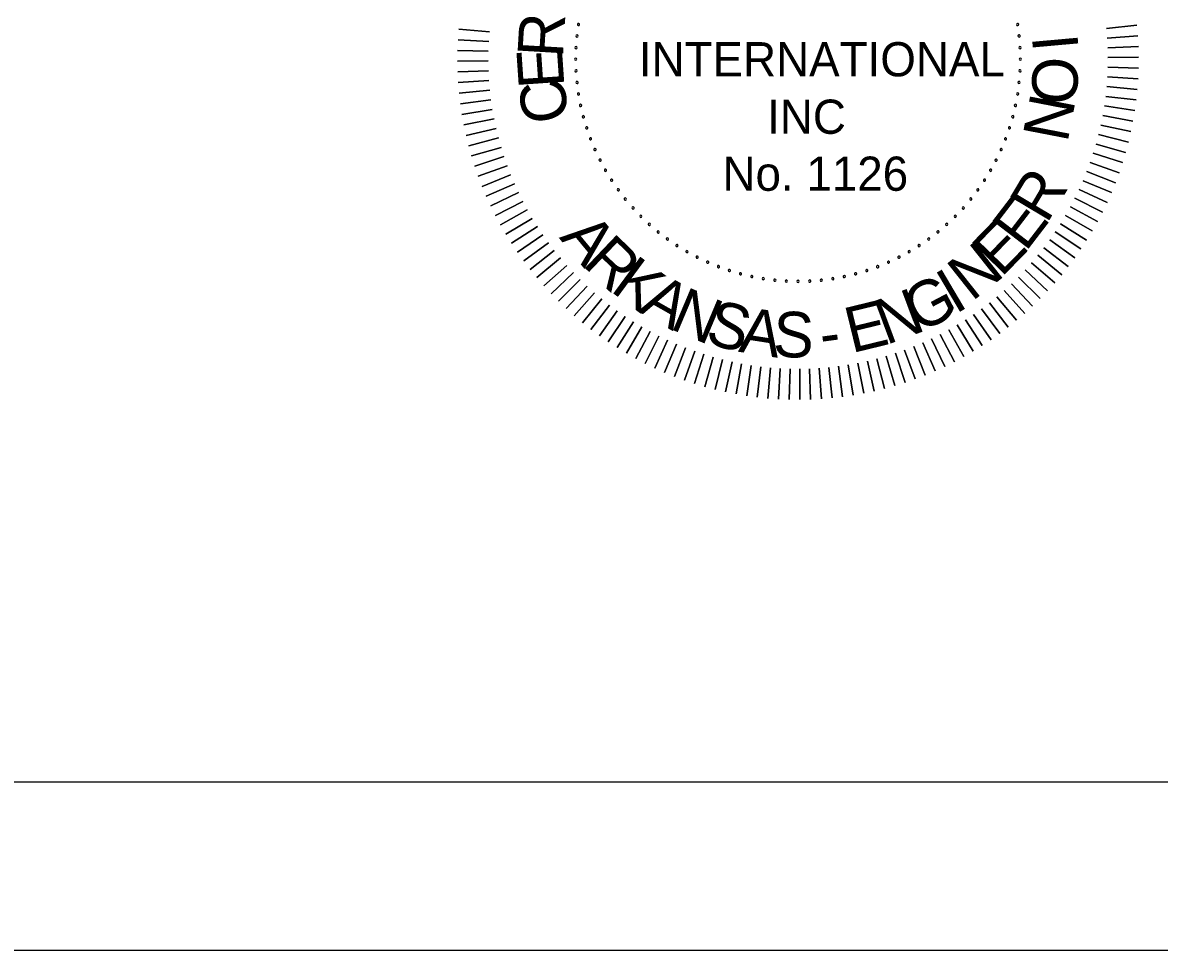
# Model space of a CAD drawing. Extents: x -0.96 to 2.36, y -0.12 to 0.92.
# Drawn here: x 1.0844 to 1.2247, y 0 to 0.1146 of the extents above; entities that cross this region are included whole.
import ezdxf

# ---------------------------------------------------------------- set-up
doc = ezdxf.new("R2010")
doc.units = 0
doc.layers.add('SHET_Border-Lines', color=7, linetype='Continuous')
doc.layers.add('STAMP_COA', color=7, linetype='Continuous')

msp = doc.modelspace()

# ---------------------------------------------------------------- linework, layer by layer
at = {"layer": 'SHET_Border-Lines'}
for points in [[(0, 0), (1.41666, 0), (1.41666, 0.91666), (0, 0.91666)], [(0.04167, 0.02083), (1.39583, 0.02083), (1.39583, 0.89583), (0.04167, 0.89583)]]:
    msp.add_lwpolyline(points, close=True, dxfattribs=at)
at = {"layer": 'STAMP_COA'}
for points in [[(1.14202, 0.11347), (1.13824, 0.11381)], [(1.13824, 0.11381), (1.14202, 0.11347)], [(1.22198, 0.11428), (1.21821, 0.1139)], [(1.21821, 0.1139), (1.22198, 0.11428)], [(1.14193, 0.11228), (1.13814, 0.11249)], [(1.13814, 0.11249), (1.14193, 0.11228)], [(1.2221, 0.11296), (1.21831, 0.1127)], [(1.21831, 0.1127), (1.2221, 0.11296)], [(1.14188, 0.11107), (1.13809, 0.11117)], [(1.13809, 0.11117), (1.14188, 0.11107)], [(1.22217, 0.11164), (1.21838, 0.1115)], [(1.21838, 0.1115), (1.22217, 0.11164)], [(1.14187, 0.10987), (1.13808, 0.10985)], [(1.13808, 0.10985), (1.14187, 0.10987)], [(1.22219, 0.11032), (1.2184, 0.1103)], [(1.2184, 0.1103), (1.22219, 0.11032)], [(1.14189, 0.10867), (1.1381, 0.10853)], [(1.1381, 0.10853), (1.14189, 0.10867)], [(1.22218, 0.109), (1.21839, 0.1091)], [(1.21839, 0.1091), (1.22218, 0.109)], [(1.14196, 0.10747), (1.13817, 0.10721)], [(1.13817, 0.10721), (1.14196, 0.10747)], [(1.22203, 0.10636), (1.21825, 0.1067)], [(1.21825, 0.1067), (1.22203, 0.10636)], [(1.22213, 0.10768), (1.21834, 0.1079)], [(1.21834, 0.1079), (1.22213, 0.10768)], [(1.14206, 0.10627), (1.13828, 0.10589)], [(1.13828, 0.10589), (1.14206, 0.10627)], [(1.22189, 0.10505), (1.21813, 0.1055)], [(1.21813, 0.1055), (1.22189, 0.10505)], [(1.1422, 0.10508), (1.13844, 0.10458)], [(1.13844, 0.10458), (1.1422, 0.10508)], [(1.14237, 0.10389), (1.13863, 0.10327)], [(1.13863, 0.10327), (1.14237, 0.10389)], [(1.22171, 0.10374), (1.21796, 0.10431)], [(1.21796, 0.10431), (1.22171, 0.10374)], [(1.14259, 0.10271), (1.13886, 0.10197)], [(1.13886, 0.10197), (1.14259, 0.10271)], [(1.22149, 0.10243), (1.21776, 0.10312)], [(1.21776, 0.10312), (1.22149, 0.10243)], [(1.14284, 0.10153), (1.13914, 0.10068)], [(1.13914, 0.10068), (1.14284, 0.10153)], [(1.22123, 0.10114), (1.21753, 0.10195)], [(1.21753, 0.10195), (1.22123, 0.10114)], [(1.14312, 0.10036), (1.13946, 0.0994)], [(1.13946, 0.0994), (1.14312, 0.10036)], [(1.22093, 0.09985), (1.21725, 0.10078)], [(1.21725, 0.10078), (1.22093, 0.09985)], [(1.14345, 0.0992), (1.13981, 0.09813)], [(1.13981, 0.09813), (1.14345, 0.0992)], [(1.22021, 0.09731), (1.21659, 0.09846)], [(1.21659, 0.09846), (1.22021, 0.09731)], [(1.22059, 0.09858), (1.21694, 0.09961)], [(1.21694, 0.09961), (1.22059, 0.09858)], [(1.14381, 0.09806), (1.14021, 0.09687)], [(1.14021, 0.09687), (1.14381, 0.09806)], [(1.1442, 0.09692), (1.14064, 0.09562)], [(1.14064, 0.09562), (1.1442, 0.09692)], [(1.21979, 0.09606), (1.21621, 0.09732)], [(1.21621, 0.09732), (1.21979, 0.09606)], [(1.14463, 0.0958), (1.14112, 0.09438)], [(1.14112, 0.09438), (1.14463, 0.0958)], [(1.21933, 0.09482), (1.21579, 0.0962)], [(1.21579, 0.0962), (1.21933, 0.09482)], [(1.1451, 0.09469), (1.14163, 0.09317)], [(1.14163, 0.09317), (1.1451, 0.09469)], [(1.21883, 0.0936), (1.21534, 0.09508)], [(1.21534, 0.09508), (1.21883, 0.0936)], [(1.1456, 0.0936), (1.14218, 0.09197)], [(1.14218, 0.09197), (1.1456, 0.0936)], [(1.21772, 0.0912), (1.21433, 0.0929)], [(1.21433, 0.0929), (1.21772, 0.0912)], [(1.21829, 0.09239), (1.21485, 0.09399)], [(1.21485, 0.09399), (1.21829, 0.09239)], [(1.14614, 0.09252), (1.14277, 0.09078)], [(1.14277, 0.09078), (1.14614, 0.09252)], [(1.1467, 0.09146), (1.14339, 0.08962)], [(1.14339, 0.08962), (1.1467, 0.09146)], [(1.2171, 0.09003), (1.21377, 0.09184)], [(1.21377, 0.09184), (1.2171, 0.09003)], [(1.14731, 0.09042), (1.14405, 0.08847)], [(1.14405, 0.08847), (1.14731, 0.09042)], [(1.21646, 0.08888), (1.21318, 0.09079)], [(1.21318, 0.09079), (1.21646, 0.08888)], [(1.14794, 0.0894), (1.14475, 0.08735)], [(1.14475, 0.08735), (1.14794, 0.0894)], [(1.21505, 0.08664), (1.2119, 0.08875)], [(1.2119, 0.08875), (1.21505, 0.08664)], [(1.21577, 0.08775), (1.21256, 0.08976)], [(1.21256, 0.08976), (1.21577, 0.08775)], [(1.14861, 0.0884), (1.14548, 0.08625)], [(1.14548, 0.08625), (1.14861, 0.0884)], [(1.1493, 0.08742), (1.14625, 0.08517)], [(1.14625, 0.08517), (1.1493, 0.08742)], [(1.2143, 0.08555), (1.21122, 0.08777)], [(1.21122, 0.08777), (1.2143, 0.08555)], [(1.15003, 0.08646), (1.14704, 0.08412)], [(1.14704, 0.08412), (1.15003, 0.08646)], [(1.21269, 0.08346), (1.20976, 0.08586)], [(1.20976, 0.08586), (1.21269, 0.08346)], [(1.21351, 0.08449), (1.2105, 0.0868)], [(1.2105, 0.0868), (1.21351, 0.08449)], [(1.15079, 0.08553), (1.14788, 0.0831)], [(1.14788, 0.0831), (1.15079, 0.08553)], [(1.15157, 0.08462), (1.14874, 0.0821)], [(1.14874, 0.0821), (1.15157, 0.08462)], [(1.21184, 0.08245), (1.20898, 0.08494)], [(1.20898, 0.08494), (1.21184, 0.08245)], [(1.15239, 0.08374), (1.14964, 0.08112)], [(1.14964, 0.08112), (1.15239, 0.08374)], [(1.15323, 0.08288), (1.15056, 0.08018)], [(1.15056, 0.08018), (1.15323, 0.08288)], [(1.21004, 0.08051), (1.20734, 0.08318)], [(1.20734, 0.08318), (1.21004, 0.08051)], [(1.21095, 0.08146), (1.20818, 0.08405)], [(1.20818, 0.08405), (1.21095, 0.08146)], [(1.1541, 0.08204), (1.15151, 0.07927)], [(1.15151, 0.07927), (1.1541, 0.08204)], [(1.20812, 0.07869), (1.2056, 0.08152)], [(1.2056, 0.08152), (1.20812, 0.07869)], [(1.2091, 0.07959), (1.20648, 0.08234)], [(1.20648, 0.08234), (1.2091, 0.07959)], [(1.1525, 0.07838), (1.15499, 0.08124)], [(1.15499, 0.08124), (1.1525, 0.07838)], [(1.15351, 0.07753), (1.15591, 0.08047)], [(1.15591, 0.08047), (1.15351, 0.07753)], [(1.20712, 0.07783), (1.20469, 0.08074)], [(1.20469, 0.08074), (1.20712, 0.07783)], [(1.15454, 0.07671), (1.15685, 0.07972)], [(1.15685, 0.07972), (1.15454, 0.07671)], [(1.1556, 0.07592), (1.15781, 0.079)], [(1.15781, 0.079), (1.1556, 0.07592)], [(1.20505, 0.0762), (1.2028, 0.07925)], [(1.2028, 0.07925), (1.20505, 0.0762)], [(1.2061, 0.077), (1.20376, 0.07998)], [(1.20376, 0.07998), (1.2061, 0.077)], [(1.15669, 0.07517), (1.1588, 0.07832)], [(1.1588, 0.07832), (1.15669, 0.07517)], [(1.1578, 0.07445), (1.15981, 0.07766)], [(1.15981, 0.07766), (1.1578, 0.07445)], [(1.20175, 0.074), (1.1998, 0.07726)], [(1.1998, 0.07726), (1.20175, 0.074)], [(1.20287, 0.0747), (1.20082, 0.07789)], [(1.20082, 0.07789), (1.20287, 0.0747)], [(1.20397, 0.07543), (1.20182, 0.07856)], [(1.20182, 0.07856), (1.20397, 0.07543)], [(1.15893, 0.07376), (1.16084, 0.07704)], [(1.16084, 0.07704), (1.15893, 0.07376)], [(1.16008, 0.07312), (1.16189, 0.07645)], [(1.16189, 0.07645), (1.16008, 0.07312)], [(1.16125, 0.0725), (1.16295, 0.07589)], [(1.16295, 0.07589), (1.16125, 0.0725)], [(1.19944, 0.07272), (1.1977, 0.07609)], [(1.1977, 0.07609), (1.19944, 0.07272)], [(1.2006, 0.07334), (1.19876, 0.07666)], [(1.19876, 0.07666), (1.2006, 0.07334)], [(1.16244, 0.07193), (1.16403, 0.07537)], [(1.16403, 0.07537), (1.16244, 0.07193)], [(1.16365, 0.07139), (1.16513, 0.07488)], [(1.16513, 0.07488), (1.16365, 0.07139)], [(1.16487, 0.07089), (1.16625, 0.07443)], [(1.16625, 0.07443), (1.16487, 0.07089)], [(1.19584, 0.07107), (1.19442, 0.07459)], [(1.19442, 0.07459), (1.19584, 0.07107)], [(1.19705, 0.07158), (1.19553, 0.07505)], [(1.19553, 0.07505), (1.19705, 0.07158)], [(1.19825, 0.07213), (1.19662, 0.07555)], [(1.19662, 0.07555), (1.19825, 0.07213)], [(1.16611, 0.07043), (1.16737, 0.07401)], [(1.16737, 0.07401), (1.16611, 0.07043)], [(1.16736, 0.07001), (1.16851, 0.07363)], [(1.16851, 0.07363), (1.16736, 0.07001)], [(1.16863, 0.06963), (1.16966, 0.07328)], [(1.16966, 0.07328), (1.16863, 0.06963)], [(1.19082, 0.06941), (1.18986, 0.07307)], [(1.18986, 0.07307), (1.19082, 0.06941)], [(1.19209, 0.06976), (1.19102, 0.0734)], [(1.19102, 0.0734), (1.19209, 0.06976)], [(1.19335, 0.07016), (1.19216, 0.07376)], [(1.19216, 0.07376), (1.19335, 0.07016)], [(1.1946, 0.07059), (1.1933, 0.07415)], [(1.1933, 0.07415), (1.1946, 0.07059)], [(1.1699, 0.06929), (1.17082, 0.07297)], [(1.17082, 0.07297), (1.1699, 0.06929)], [(1.17119, 0.06899), (1.172, 0.07269)], [(1.172, 0.07269), (1.17119, 0.06899)], [(1.17248, 0.06873), (1.17317, 0.07246)], [(1.17317, 0.07246), (1.17248, 0.06873)], [(1.17379, 0.06851), (1.17436, 0.07226)], [(1.17436, 0.07226), (1.17379, 0.06851)], [(1.1751, 0.06833), (1.17555, 0.07209)], [(1.17555, 0.07209), (1.1751, 0.06833)], [(1.17641, 0.06819), (1.17675, 0.07197)], [(1.17675, 0.07197), (1.17641, 0.06819)], [(1.17773, 0.06809), (1.17794, 0.07188)], [(1.17794, 0.07188), (1.17773, 0.06809)], [(1.17905, 0.06804), (1.17915, 0.07183)], [(1.17915, 0.07183), (1.17905, 0.06804)], [(1.18037, 0.06803), (1.18035, 0.07182)], [(1.18035, 0.07182), (1.18037, 0.06803)], [(1.18169, 0.06805), (1.18155, 0.07185)], [(1.18155, 0.07185), (1.18169, 0.06805)], [(1.18301, 0.06812), (1.18275, 0.07191)], [(1.18275, 0.07191), (1.18301, 0.06812)], [(1.18433, 0.06824), (1.18395, 0.07201)], [(1.18395, 0.07201), (1.18433, 0.06824)], [(1.18564, 0.06839), (1.18514, 0.07215)], [(1.18514, 0.07215), (1.18564, 0.06839)], [(1.18695, 0.06858), (1.18633, 0.07232)], [(1.18633, 0.07232), (1.18695, 0.06858)], [(1.18825, 0.06882), (1.18751, 0.07254)], [(1.18751, 0.07254), (1.18825, 0.06882)], [(1.18954, 0.06909), (1.18869, 0.07279)], [(1.18869, 0.07279), (1.18954, 0.06909)]]:
    msp.add_lwpolyline(points, dxfattribs=at)
for centre, start, end in [((1.15302, 0.11438), 81, 261), ((1.15302, 0.11438), 261, 81), ((1.20725, 0.11438), 99, 279), ((1.20725, 0.11438), 279, 99), ((1.15284, 0.11295), 84, 264), ((1.15284, 0.11295), 264, 84), ((1.20743, 0.11295), 96, 276), ((1.20743, 0.11295), 276, 96), ((1.15272, 0.11152), 87, 267), ((1.15272, 0.11152), 267, 87), ((1.20755, 0.11152), 93, 273), ((1.20755, 0.11152), 273, 93), ((1.15268, 0.11009), 90, 270), ((1.15268, 0.11009), 270, 90), ((1.20758, 0.11009), 90, 270), ((1.20758, 0.11009), 270, 90), ((1.15272, 0.10865), 93, 273), ((1.15272, 0.10865), 273, 93), ((1.20755, 0.10865), 87, 267), ((1.20755, 0.10865), 267, 87), ((1.15284, 0.10722), 96, 276), ((1.15284, 0.10722), 276, 96), ((1.20743, 0.10722), 84, 264), ((1.20743, 0.10722), 264, 84), ((1.15302, 0.10579), 99, 279), ((1.15302, 0.10579), 279, 99), ((1.20725, 0.10579), 81, 261), ((1.20725, 0.10579), 261, 81), ((1.15328, 0.10438), 102, 282), ((1.15328, 0.10438), 282, 102), ((1.20698, 0.10438), 78, 258), ((1.20698, 0.10438), 258, 78), ((1.15362, 0.10298), 105, 285), ((1.15362, 0.10298), 285, 105), ((1.20665, 0.10298), 75, 255), ((1.20665, 0.10298), 255, 75), ((1.15403, 0.1016), 108, 288), ((1.15403, 0.1016), 288, 108), ((1.20624, 0.1016), 72, 252), ((1.20624, 0.1016), 252, 72), ((1.15451, 0.10025), 111, 291), ((1.15451, 0.10025), 291, 111), ((1.20576, 0.10025), 69, 249), ((1.20576, 0.10025), 249, 69), ((1.15506, 0.09892), 114, 294), ((1.15506, 0.09892), 294, 114), ((1.20521, 0.09892), 66, 246), ((1.20521, 0.09892), 246, 66), ((1.15568, 0.09762), 117, 297), ((1.15568, 0.09762), 297, 117), ((1.20459, 0.09762), 63, 243), ((1.20459, 0.09762), 243, 63), ((1.15636, 0.09636), 120, 300), ((1.15636, 0.09636), 300, 120), ((1.20391, 0.09636), 60, 240), ((1.20391, 0.09636), 240, 60), ((1.15711, 0.09514), 123, 303), ((1.15711, 0.09514), 303, 123), ((1.15793, 0.09395), 126, 306), ((1.15793, 0.09395), 306, 126), ((1.20234, 0.09395), 54, 234), ((1.20234, 0.09395), 234, 54), ((1.20316, 0.09514), 57, 237), ((1.20316, 0.09514), 237, 57), ((1.1588, 0.09281), 129, 309), ((1.1588, 0.09281), 309, 129), ((1.20147, 0.09281), 51, 231), ((1.20147, 0.09281), 231, 51), ((1.15974, 0.09172), 132, 312), ((1.15974, 0.09172), 312, 132), ((1.20053, 0.09172), 48, 228), ((1.20053, 0.09172), 228, 48), ((1.16072, 0.09068), 135, 315), ((1.16072, 0.09068), 315, 135), ((1.19954, 0.09068), 45, 225), ((1.19954, 0.09068), 225, 45), ((1.16177, 0.08969), 138, 318), ((1.16177, 0.08969), 318, 138), ((1.16286, 0.08875), 141, 321), ((1.16286, 0.08875), 321, 141), ((1.19741, 0.08875), 39, 219), ((1.19741, 0.08875), 219, 39), ((1.1985, 0.08969), 42, 222), ((1.1985, 0.08969), 222, 42), ((1.164, 0.08788), 144, 324), ((1.164, 0.08788), 324, 144), ((1.16518, 0.08706), 147, 327), ((1.16518, 0.08706), 327, 147), ((1.19508, 0.08706), 33, 213), ((1.19508, 0.08706), 213, 33), ((1.19627, 0.08788), 36, 216), ((1.19627, 0.08788), 216, 36), ((1.16641, 0.08631), 150, 330), ((1.16641, 0.08631), 330, 150), ((1.16767, 0.08563), 153, 333), ((1.16767, 0.08563), 333, 153), ((1.1926, 0.08563), 27, 207), ((1.1926, 0.08563), 207, 27), ((1.19386, 0.08631), 30, 210), ((1.19386, 0.08631), 210, 30), ((1.16897, 0.08501), 156, 336), ((1.16897, 0.08501), 336, 156), ((1.1703, 0.08446), 159, 339), ((1.1703, 0.08446), 339, 159), ((1.18997, 0.08446), 21, 201), ((1.18997, 0.08446), 201, 21), ((1.1913, 0.08501), 24, 204), ((1.1913, 0.08501), 204, 24), ((1.17165, 0.08398), 162, 342), ((1.17165, 0.08398), 342, 162), ((1.17303, 0.08357), 345, 165), ((1.17303, 0.08357), 165, 345), ((1.17443, 0.08324), 348, 168), ((1.17443, 0.08324), 168, 348), ((1.17584, 0.08297), 351, 171), ((1.17584, 0.08297), 171, 351), ((1.17727, 0.08279), 354, 174), ((1.1787, 0.08267), 357, 177), ((1.18157, 0.08267), 3, 183), ((1.183, 0.08279), 6, 186), ((1.18443, 0.08297), 9, 189), ((1.18443, 0.08297), 189, 9), ((1.18584, 0.08324), 12, 192), ((1.18584, 0.08324), 192, 12), ((1.18724, 0.08357), 15, 195), ((1.18724, 0.08357), 195, 15), ((1.18862, 0.08398), 18, 198), ((1.18862, 0.08398), 198, 18), ((1.17727, 0.08279), 174, 354), ((1.1787, 0.08267), 177, 357), ((1.18013, 0.08264), 0, 180), ((1.18013, 0.08264), 180, 0), ((1.18157, 0.08267), 183, 3), ((1.183, 0.08279), 186, 6)]:
    msp.add_arc(centre, 0.000141, start, end, dxfattribs=at)

# ---------------------------------------------------------------- texts
for s, rotation, p in [('R', 86.6268, (1.15109, 0.11021)), ('I', 275.1216, (1.209, 0.11293)), ('E', 93.9203, (1.15129, 0.10669)), ('O', 267.0743, (1.2092, 0.11051)), ('C', 101.2137, (1.15201, 0.10277)), ('N', 259.0269, (1.2089, 0.10608)), ('R', 59.2262, (1.21085, 0.08966)), ('E', 52.4765, (1.20823, 0.08619)), ('A', 309.5859, (1.15057, 0.08803)), ('E', 45.7268, (1.20523, 0.08305)), ('R', 316.3356, (1.15337, 0.08471)), ('N', 38.4196, (1.20159, 0.08008)), ('K', 323.6428, (1.15682, 0.08151)), ('G', 27.7404, (1.19509, 0.07616)), ('I', 30.5495, (1.19954, 0.07853)), ('A', 330.3925, (1.16034, 0.07896)), ('N', 337.1422, (1.16413, 0.07685)), ('N', 20.4332, (1.19099, 0.07474)), ('S', 344.4494, (1.16849, 0.07509)), ('E', 13.6835, (1.18674, 0.07375)), ('A', 351.1991, (1.17268, 0.07396)), ('S', 357.9489, (1.17698, 0.07334)), ('-', 7.5077, (1.18313, 0.07332))]:
    msp.add_text(s, height=0.00563, rotation=rotation, dxfattribs=at).set_placement(p)
for s, height, p in [(' INTERNATIONAL', 0.0042254, (1.1589, 0.10797)), ('INC', 0.004225, (1.17631, 0.10087)), (' No. 1126', 0.004225, (1.16923, 0.09383))]:
    msp.add_text(s, height=height, dxfattribs=at).set_placement(p)

doc.saveas('drawing.dxf')
